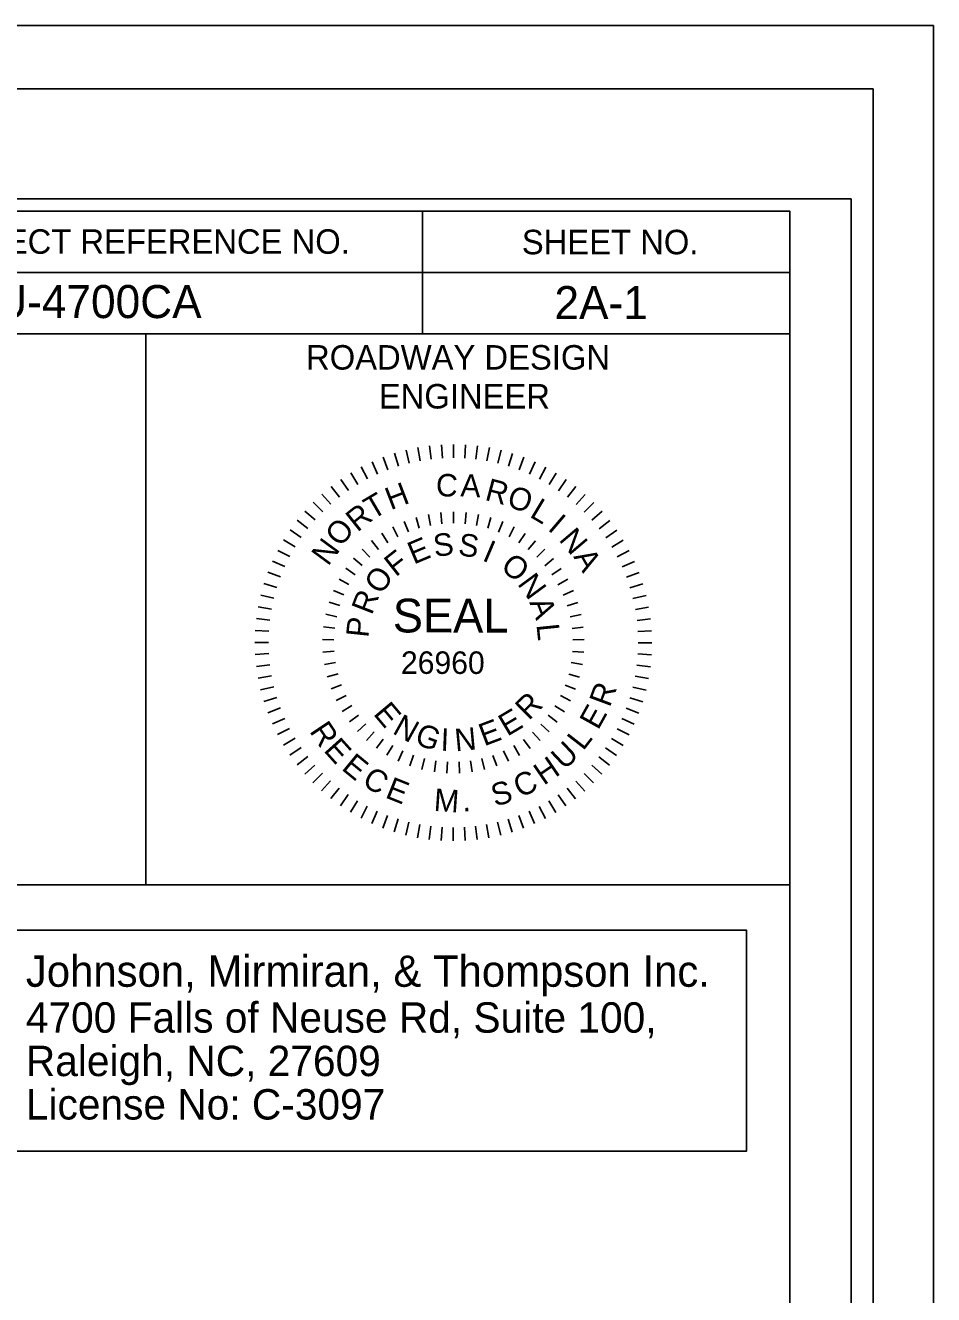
# Model space of a CAD drawing. Extents: x 2294455 to 2294842, y 719496 to 719941.
# Drawn here: x 2294756.7 to 2294793.8, y 719666.9 to 719718.8 of the extents above; entities that cross this region are included whole.
import ezdxf

# ---------------------------------------------------------------- set-up
doc = ezdxf.new("R2010")
doc.units = 0
for name, color, linetype in [('Default', 7, 'Continuous'), ('Old_Level_1', 7, 'Continuous'), ('Sheet Cutting Line CELL', 7, 'Continuous'), ('Sheet Data Field CELL', 7, 'Continuous'), ('Sheet Plan CELL', 7, 'Continuous'), ('Sheet Plot Border Inside CELL', 7, 'Continuous'), ('Sheet Plot Border Outside CELL', 7, 'Continuous'), ('Sheet Typical CELL', 7, 'Continuous')]:
    doc.layers.add(name, color=color, linetype=linetype)

msp = doc.modelspace()

# ---------------------------------------------------------------- linework, layer by layer
at = {"layer": 'Default'}
for p, q in [((2294772.737, 719701.514), (2294772.836, 719700.971)), ((2294773.221, 719701.587), (2294773.286, 719701.039)), ((2294773.708, 719701.631), (2294773.74, 719701.08)), ((2294774.197, 719701.645), (2294774.197, 719701.093)), ((2294774.687, 719701.63), (2294774.653, 719701.079)), ((2294775.174, 719701.585), (2294775.107, 719701.038)), ((2294775.657, 719701.512), (2294775.557, 719700.969)), ((2294771.324, 719701.122), (2294771.52, 719700.605)), ((2294771.787, 719701.281), (2294771.95, 719700.753)), ((2294772.259, 719701.412), (2294772.39, 719700.876)), ((2294776.135, 719701.408), (2294776.003, 719700.872)), ((2294776.607, 719701.277), (2294776.442, 719700.749)), ((2294777.069, 719701.117), (2294776.872, 719700.6)), ((2294770.005, 719700.481), (2294770.291, 719700.008)), ((2294770.432, 719700.721), (2294770.688, 719700.232)), ((2294770.873, 719700.934), (2294771.098, 719700.431)), ((2294777.521, 719700.928), (2294777.294, 719700.425)), ((2294777.961, 719700.714), (2294777.703, 719700.225)), ((2294778.387, 719700.473), (2294778.1, 719700.001)), ((2294769.594, 719700.216), (2294769.908, 719699.761)), ((2294778.797, 719700.207), (2294778.483, 719699.753)), ((2294768.824, 719699.613), (2294769.19, 719699.2)), ((2294769.201, 719699.926), (2294769.54, 719699.491)), ((2294779.191, 719699.917), (2294778.85, 719699.483)), ((2294779.567, 719699.603), (2294779.2, 719699.19)), ((2294768.132, 719698.922), (2294768.545, 719698.556)), ((2294768.468, 719699.278), (2294768.857, 719698.887)), ((2294779.922, 719699.267), (2294779.532, 719698.878)), ((2294767.818, 719698.546), (2294768.252, 719698.206)), ((2294772.181, 719698.492), (2294772.354, 719698.065)), ((2294772.668, 719698.663), (2294772.799, 719698.221)), ((2294773.169, 719698.785), (2294773.257, 719698.334)), ((2294773.679, 719698.859), (2294773.723, 719698.402)), ((2294774.195, 719698.884), (2294774.194, 719698.424)), ((2294774.194, 719698.424), (2294774.195, 719698.884)), ((2294774.71, 719698.858), (2294774.665, 719698.401)), ((2294775.22, 719698.783), (2294775.132, 719698.332)), ((2294775.721, 719698.66), (2294775.589, 719698.218)), ((2294776.208, 719698.488), (2294776.034, 719698.062)), ((2294780.257, 719698.911), (2294779.844, 719698.545)), ((2294780.571, 719698.534), (2294780.136, 719698.195)), ((2294767.528, 719698.153), (2294767.982, 719697.839)), ((2294771.268, 719698.014), (2294771.52, 719697.628)), ((2294771.713, 719698.275), (2294771.926, 719697.867)), ((2294776.675, 719698.27), (2294776.461, 719697.863)), ((2294777.12, 719698.008), (2294776.867, 719697.623)), ((2294780.86, 719698.141), (2294780.406, 719697.827)), ((2294767.262, 719697.742), (2294767.734, 719697.456)), ((2294770.464, 719697.369), (2294770.786, 719697.039)), ((2294770.85, 719697.711), (2294771.138, 719697.351)), ((2294777.537, 719697.704), (2294777.248, 719697.345)), ((2294777.922, 719697.362), (2294777.6, 719697.033)), ((2294781.126, 719697.73), (2294780.653, 719697.444)), ((2294766.807, 719696.876), (2294767.31, 719696.65)), ((2294767.021, 719697.316), (2294767.51, 719697.059)), ((2294770.113, 719696.992), (2294770.464, 719696.695)), ((2294778.273, 719696.984), (2294777.922, 719696.688)), ((2294781.366, 719697.303), (2294780.876, 719697.047)), ((2294781.579, 719696.862), (2294781.075, 719696.637)), ((2294766.618, 719696.424), (2294767.135, 719696.228)), ((2294769.799, 719696.582), (2294770.177, 719696.32)), ((2294778.586, 719696.574), (2294778.207, 719696.312)), ((2294781.767, 719696.41), (2294781.25, 719696.215)), ((2294766.458, 719695.963), (2294766.986, 719695.798)), ((2294769.527, 719696.145), (2294769.928, 719695.919)), ((2294778.857, 719696.136), (2294778.456, 719695.912)), ((2294781.926, 719695.948), (2294781.397, 719695.785)), ((2294766.326, 719695.49), (2294766.863, 719695.359)), ((2294769.297, 719695.682), (2294769.719, 719695.498)), ((2294779.086, 719695.673), (2294778.664, 719695.489)), ((2294782.057, 719695.476), (2294781.52, 719695.345)), ((2294766.223, 719695.013), (2294766.766, 719694.913)), ((2294769.114, 719695.199), (2294769.552, 719695.057)), ((2294779.268, 719695.19), (2294778.83, 719695.049)), ((2294782.159, 719694.998), (2294781.616, 719694.899)), ((2294766.15, 719694.529), (2294766.697, 719694.462)), ((2294768.978, 719694.702), (2294769.427, 719694.602)), ((2294779.404, 719694.692), (2294778.954, 719694.594)), ((2294782.231, 719694.514), (2294781.684, 719694.448)), ((2294766.105, 719694.042), (2294766.656, 719694.008)), ((2294768.891, 719694.193), (2294769.347, 719694.138)), ((2294779.49, 719694.184), (2294779.034, 719694.129)), ((2294782.275, 719694.027), (2294781.724, 719693.994)), ((2294766.09, 719693.553), (2294766.642, 719693.552)), ((2294768.853, 719693.679), (2294769.312, 719693.667)), ((2294779.527, 719693.669), (2294779.067, 719693.658)), ((2294782.29, 719693.538), (2294781.738, 719693.538)), ((2294766.104, 719693.063), (2294766.655, 719693.096)), ((2294768.865, 719693.163), (2294769.323, 719693.196)), ((2294768.927, 719692.651), (2294769.38, 719692.728)), ((2294779, 719692.735), (2294779.454, 719692.659)), ((2294779.514, 719693.154), (2294779.056, 719693.187)), ((2294782.274, 719693.048), (2294781.724, 719693.082)), ((2294766.148, 719692.576), (2294766.696, 719692.642)), ((2294766.221, 719692.093), (2294766.764, 719692.191)), ((2294769.037, 719692.147), (2294769.481, 719692.267)), ((2294779.34, 719692.137), (2294778.896, 719692.259)), ((2294782.156, 719692.078), (2294781.613, 719692.178)), ((2294782.229, 719692.561), (2294781.682, 719692.628)), ((2294766.323, 719691.614), (2294766.859, 719691.745)), ((2294769.196, 719691.656), (2294769.627, 719691.819)), ((2294779.18, 719691.647), (2294778.75, 719691.811)), ((2294782.053, 719691.6), (2294781.517, 719691.732)), ((2294766.454, 719691.142), (2294766.982, 719691.306)), ((2294769.402, 719691.184), (2294769.814, 719691.388)), ((2294778.973, 719691.175), (2294778.561, 719691.38)), ((2294781.921, 719691.128), (2294781.393, 719691.293)), ((2294766.613, 719690.68), (2294767.13, 719690.876)), ((2294769.652, 719690.733), (2294770.043, 719690.975)), ((2294778.722, 719690.725), (2294778.331, 719690.967)), ((2294781.761, 719690.666), (2294781.245, 719690.863)), ((2294766.801, 719690.228), (2294767.304, 719690.453)), ((2294769.945, 719690.307), (2294770.311, 719690.586)), ((2294770.277, 719689.913), (2294770.614, 719690.226)), ((2294778.095, 719689.906), (2294777.759, 719690.219)), ((2294778.429, 719690.299), (2294778.063, 719690.579)), ((2294781.573, 719690.214), (2294781.07, 719690.441)), ((2294767.014, 719689.788), (2294767.503, 719690.044)), ((2294767.254, 719689.361), (2294767.726, 719689.647)), ((2294770.645, 719689.553), (2294770.951, 719689.897)), ((2294771.048, 719689.229), (2294771.318, 719689.601)), ((2294777.324, 719689.224), (2294777.054, 719689.596)), ((2294777.727, 719689.546), (2294777.421, 719689.891)), ((2294781.118, 719689.348), (2294780.646, 719689.635)), ((2294781.359, 719689.774), (2294780.87, 719690.031)), ((2294767.519, 719688.95), (2294767.974, 719689.263)), ((2294771.479, 719688.946), (2294771.713, 719689.343)), ((2294771.936, 719688.706), (2294772.13, 719689.124)), ((2294776.435, 719688.702), (2294776.241, 719689.12)), ((2294776.892, 719688.941), (2294776.659, 719689.338)), ((2294780.852, 719688.938), (2294780.398, 719689.252)), ((2294767.809, 719688.556), (2294768.244, 719688.896)), ((2294768.122, 719688.179), (2294768.535, 719688.545)), ((2294772.414, 719688.511), (2294772.567, 719688.945)), ((2294773.015, 719688.81), (2294772.904, 719688.363)), ((2294773.414, 719688.263), (2294773.48, 719688.718)), ((2294773.927, 719688.213), (2294773.949, 719688.672)), ((2294774.443, 719688.212), (2294774.421, 719688.672)), ((2294774.956, 719688.262), (2294774.89, 719688.717)), ((2294775.463, 719688.361), (2294775.352, 719688.808)), ((2294775.957, 719688.507), (2294775.804, 719688.942)), ((2294780.561, 719688.544), (2294780.127, 719688.885)), ((2294768.457, 719687.823), (2294768.848, 719688.213)), ((2294779.912, 719687.813), (2294779.522, 719688.203)), ((2294780.247, 719688.168), (2294779.835, 719688.535)), ((2294768.813, 719687.487), (2294769.179, 719687.9)), ((2294769.189, 719687.173), (2294769.529, 719687.608)), ((2294779.179, 719687.164), (2294778.839, 719687.599)), ((2294779.556, 719687.478), (2294779.19, 719687.891)), ((2294769.582, 719686.883), (2294769.896, 719687.337)), ((2294769.992, 719686.617), (2294770.279, 719687.089)), ((2294778.374, 719686.609), (2294778.088, 719687.082)), ((2294778.785, 719686.875), (2294778.472, 719687.329)), ((2294770.419, 719686.376), (2294770.676, 719686.865)), ((2294770.859, 719686.162), (2294771.085, 719686.665)), ((2294771.31, 719685.974), (2294771.507, 719686.49)), ((2294777.055, 719685.968), (2294776.859, 719686.485)), ((2294777.507, 719686.156), (2294777.281, 719686.659)), ((2294777.947, 719686.369), (2294777.691, 719686.859)), ((2294771.772, 719685.814), (2294771.937, 719686.342)), ((2294772.244, 719685.682), (2294772.376, 719686.218)), ((2294772.722, 719685.579), (2294772.822, 719686.122)), ((2294773.206, 719685.505), (2294773.273, 719686.053)), ((2294773.693, 719685.461), (2294773.727, 719686.011)), ((2294774.182, 719685.445), (2294774.183, 719685.997)), ((2294774.672, 719685.46), (2294774.639, 719686.011)), ((2294775.159, 719685.504), (2294775.093, 719686.051)), ((2294775.642, 719685.576), (2294775.544, 719686.119)), ((2294776.121, 719685.678), (2294775.99, 719686.215)), ((2294776.593, 719685.809), (2294776.429, 719686.337))]:
    msp.add_line(p, q, dxfattribs=at)
at = {"layer": 'Old_Level_1'}
msp.add_lwpolyline([(2294736.145, 719672.776), (2294786.155, 719672.776), (2294786.155, 719681.8), (2294736.145, 719681.8)], close=True, dxfattribs=at)
at = {"layer": 'Sheet Cutting Line CELL'}
msp.add_line((2294791.324, 719716.169), (2294454.524, 719716.169), dxfattribs=at)
at = {"layer": 'Sheet Plan CELL'}
for points in [[(2294761.64, 719683.659), (2294735.355, 719683.659), (2294735.355, 719706.159), (2294761.64, 719706.159)], [(2294787.924, 719683.659), (2294761.64, 719683.659), (2294761.64, 719706.159), (2294787.924, 719706.159)]]:
    msp.add_lwpolyline(points, dxfattribs=at)
at = {"layer": 'Sheet Plot Border Inside CELL'}
msp.add_lwpolyline([(2294790.424, 719711.679), (2294457.124, 719711.679), (2294457.124, 719500.659), (2294790.424, 719500.659)], close=True, dxfattribs=at)
at = {"layer": 'Sheet Plot Border Outside CELL'}
for points in [[(2294793.79, 719718.758), (2294456.99, 719718.758), (2294456.99, 719498.758), (2294793.79, 719498.758)], [(2294791.324, 719716.169), (2294454.524, 719716.169), (2294454.524, 719496.169), (2294791.324, 719496.169)]]:
    msp.add_lwpolyline(points, close=True, dxfattribs=at)
at = {"layer": 'Sheet Typical CELL'}
for p, q in [((2294772.924, 719711.159), (2294772.924, 719706.159)), ((2294747.914, 719708.659), (2294787.924, 719708.659)), ((2294747.914, 719706.159), (2294767.924, 719706.159))]:
    msp.add_line(p, q, dxfattribs=at)
for points in [[(2294787.924, 719711.169), (2294487.924, 719711.169), (2294487.924, 719501.169), (2294787.924, 719501.169)], [(2294747.914, 719711.169), (2294787.924, 719711.169), (2294787.924, 719706.159), (2294747.914, 719706.159)]]:
    msp.add_lwpolyline(points, close=True, dxfattribs=at)

# ---------------------------------------------------------------- texts
at = {"layer": 'Default'}
for s, height, rotation, p in [('H', 0.919, 21.0146, (2294771.629, 719698.949)), ('C', 0.919, 357.3039, (2294773.46, 719699.538)), ('A', 0.919, 357.3039, (2294774.464, 719699.519)), ('R', 0.919, 345.2946, (2294775.438, 719699.382)), ('T', 0.919, 30.4466, (2294770.889, 719698.549)), ('O', 0.919, 342.2378, (2294776.329, 719699.117)), ('L', 0.919, 329.1015, (2294777.264, 719698.706)), ('R', 0.919, 38.6075, (2294770.27, 719698.035)), ('O', 0.919, 51.6643, (2294769.603, 719697.416)), ('I', 0.919, 319.5261, (2294778.005, 719698.172)), ('S', 0.919, 7.5951, (2294773.434, 719697.042)), ('S', 0.919, 352.2989, (2294774.353, 719697.118)), ('N', 0.919, 310.2316, (2294778.465, 719697.738)), ('N', 0.919, 53.6237, (2294769.074, 719696.64)), ('F', 0.919, 38.1876, (2294771.834, 719696.207)), ('E', 0.919, 22.8914, (2294772.571, 719696.727)), ('I', 0.919, 337.0026, (2294775.33, 719696.918)), ('O', 0.919, 321.7064, (2294776.071, 719696.559)), ('A', 0.919, 300.4641, (2294779.072, 719697.058)), ('O', 0.919, 53.4838, (2294771.222, 719695.467)), ('N', 0.919, 306.4101, (2294776.779, 719695.943)), ('R', 0.919, 68.7801, (2294770.858, 719694.641)), ('SEAL', 1.3802, 359.947, (2294771.717, 719693.962)), ('A', 0.919, 291.1139, (2294777.283, 719695.189)), ('P', 0.919, 84.0763, (2294770.718, 719693.73)), ('L', 0.919, 275.8176, (2294777.579, 719694.279)), ('26960', 0.9194, 359.947, (2294772.049, 719692.27)), ('R', 0.919, 69.6194, (2294780.57, 719690.874)), ('E', 0.919, 310.0171, (2294770.892, 719690.628)), ('R', 0.919, 44.5119, (2294777.267, 719690.338)), ('E', 0.919, 30.7408, (2294776.39, 719689.698)), ('E', 0.919, 60.9466, (2294780.096, 719689.946)), ('R', 0.919, 303.882, (2294768.294, 719689.927)), ('N', 0.919, 330.8721, (2294771.663, 719689.861)), ('G', 0.919, 339.6384, (2294772.563, 719689.429)), ('E', 0.919, 20.7549, (2294775.446, 719689.306)), ('E', 0.919, 311.9538, (2294768.863, 719689.133)), ('I', 0.919, 357.7332, (2294773.657, 719689.134)), ('N', 0.919, 5.3628, (2294774.281, 719689.102)), ('L', 0.919, 52.154, (2294779.487, 719689.1)), ('U', 0.919, 43.2714, (2294778.716, 719688.315)), ('E', 0.919, 320.5966, (2294769.586, 719688.382)), ('H', 0.919, 34.3888, (2294777.878, 719687.695)), ('C', 0.919, 329.2691, (2294770.415, 719687.749)), ('E', 0.919, 338.2416, (2294771.368, 719687.23)), ('C', 0.919, 25.5662, (2294776.917, 719687.189)), ('M', 0.919, 356.0369, (2294773.372, 719686.674)), ('S', 0.919, 16.5636, (2294775.889, 719686.841)), ('.', 0.919, 3.7793, (2294774.572, 719686.645))]:
    msp.add_text(s, height=height, rotation=rotation, dxfattribs=at).set_placement(p)
at = {"layer": 'Old_Level_1'}
for s, height, p in [('Johnson, Mirmiran, & Thompson Inc.', 1.2778, (2294756.74, 719679.489)), ('4700 Falls of Neuse Rd, Suite 100, ', 1.24129, (2294756.74, 719677.614)), ('Raleigh, NC, 27609', 1.24129, (2294756.74, 719675.84)), ('License No: C-3097', 1.24129, (2294756.74, 719674.067))]:
    msp.add_text(s, height=height, dxfattribs=at).set_placement(p)
at = {"layer": 'Sheet Data Field CELL'}
msp.add_text('U-4700CA', height=1.35, rotation=360, dxfattribs=at).set_placement((2294755.487, 719706.802))
msp.add_text('2A-1', height=1.35, dxfattribs=at).set_placement((2294778.314, 719706.76))
at = {"layer": 'Sheet Plan CELL'}
for s, height, p in [('ROADWAY DESIGN', 1.00002, (2294768.176, 719704.699)), ('ENGINEER', 1, (2294771.146, 719703.109))]:
    msp.add_text(s, height=height, dxfattribs=at).set_placement(p)
at = {"layer": 'Sheet Typical CELL'}
for s, height, p in [('PROJECT REFERENCE NO.', 1.00002, (2294752.354, 719709.429)), ('SHEET NO.', 1, (2294776.984, 719709.409))]:
    msp.add_text(s, height=height, dxfattribs=at).set_placement(p)

doc.saveas('drawing.dxf')
